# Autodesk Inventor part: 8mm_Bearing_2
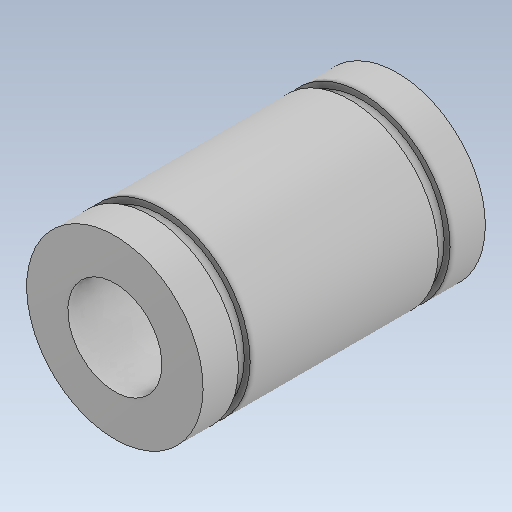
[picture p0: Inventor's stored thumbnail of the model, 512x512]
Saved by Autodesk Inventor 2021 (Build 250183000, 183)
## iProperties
Created: 2026-10
Part Number: 8mm_Bearing_2
Material: Generic
Document SubType Name: Modeling
Designer: hp
Density: 1 g/cm^3
Appearance: Default
Author: hp
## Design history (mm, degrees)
feature "Body1"
body "Solid1"
